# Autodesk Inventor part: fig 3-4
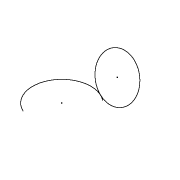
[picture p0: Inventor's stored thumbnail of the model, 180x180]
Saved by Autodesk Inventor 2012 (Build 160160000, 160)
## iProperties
Created: 2009-11
Part Number: fig 3-4
Document SubType Name: Modeling
Designer: Sham
Density: 1 g/cm^3
Material: Default
Author: Sham
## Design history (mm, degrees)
sketch "Sketch1"
  geometry: A1 r 10.623 centre (-1.113, -21.203) between (5.463, -12.861) and (-5.537, -30.861); 1 further point; 1 other entity
  constraints: 2 point on circle, 1 centre point, 4 other
